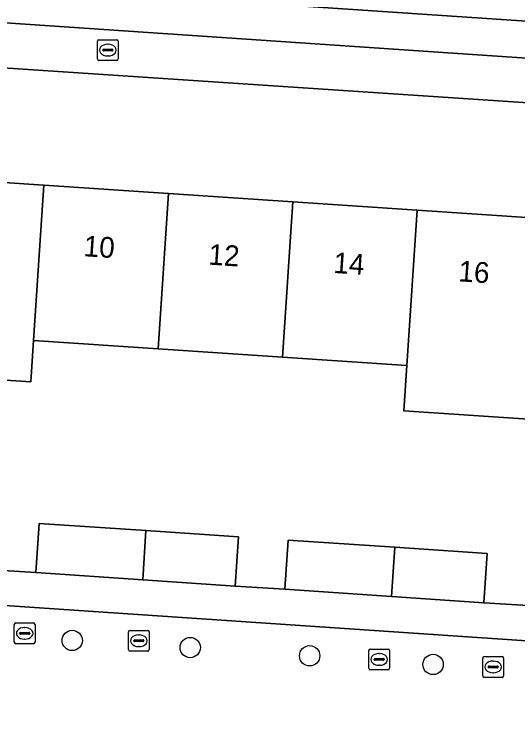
# Model space of a CAD drawing. Extents: x 161848 to 162726, y 385382 to 386521.
# Drawn here: x 162073.24 to 162097.46, y 385706.38 to 385740.75 of the extents above; entities that cross this region are included whole.
import ezdxf

# ---------------------------------------------------------------- set-up
doc = ezdxf.new("R2010")
doc.units = 0
for name, color, linetype in [('IMGEO_Boom', 7, 'Continuous'), ('IMGEO_Brandkraan', 7, 'Continuous'), ('IMGEO_Erf', 7, 'Continuous'), ('IMGEO_Kolk', 7, 'Continuous'), ('IMGEO_Pand', 7, 'Continuous'), ('IMGEO_Pand_nummerreeks', 7, 'Continuous'), ('IMGEO_Parkeervlak_open', 7, 'Continuous'), ('IMGEO_Rijbaan_lokaal_gesloten', 7, 'Continuous'), ('IMGEO_Voetpad_open', 7, 'Continuous')]:
    doc.layers.add(name, color=color, linetype=linetype)

msp = doc.modelspace()

# ---------------------------------------------------------------- linework, layer by layer
at = {"layer": 'IMGEO_Boom'}
for centre in [(162076.032, 385710.625), (162081.706, 385710.283), (162087.454, 385709.885), (162093.389, 385709.468)]:
    msp.add_circle(centre, 0.489, dxfattribs=at)
at = {"layer": 'IMGEO_Brandkraan'}
for p, q in [((162077.243, 385738.602), (162077.243, 385739.454)), ((162077.318, 385739.528), (162078.17, 385739.528)), ((162077.731, 385739.308), (162077.756, 385739.308)), ((162078.244, 385739.454), (162078.244, 385738.602)), ((162077.502, 385739.022), (162077.502, 385739.034)), ((162077.94, 385738.985), (162077.542, 385738.985)), ((162077.545, 385739.071), (162077.943, 385739.071)), ((162077.986, 385739.034), (162077.986, 385739.022)), ((162077.754, 385738.748), (162077.729, 385738.748)), ((162078.17, 385738.528), (162077.318, 385738.528))]:
    msp.add_line(p, q, dxfattribs=at)
for points in [[(162077.243, 385738.602), (162077.243, 385739.454)], [(162077.318, 385739.528), (162078.17, 385739.528)], [(162078.244, 385739.454), (162078.244, 385738.602)], [(162078.17, 385738.528), (162077.318, 385738.528)]]:
    msp.add_lwpolyline(points, dxfattribs=at)
for centre, radius, start, end in [((162077.32, 385739.452), 0.0765, 91.552, 178.448), ((162077.32, 385739.452), 0.0765, 91.552, 178.448), ((162078.168, 385739.452), 0.0765, 1.552, 88.448), ((162078.168, 385739.452), 0.0765, 1.552, 88.448), ((162077.542, 385739.031), 0.0403, 85.8775, 175.7526), ((162077.539, 385739.021), 0.0366, 178.938, 274.7102), ((162077.943, 385739.028), 0.043, 264.8664, 352.4533), ((162077.947, 385739.033), 0.0386, 1.7309, 96.639), ((162077.32, 385738.604), 0.0765, 181.552, 268.448), ((162077.32, 385738.604), 0.0765, 181.552, 268.448), ((162078.168, 385738.604), 0.0765, 271.552, 358.448), ((162078.168, 385738.604), 0.0765, 271.552, 358.448)]:
    msp.add_arc(centre, radius, start, end, dxfattribs=at)
for centre, major_axis, ratio, start_param, end_param in [((162077.73, 385739.028), (-0.387, 0.002), 0.722429, 4.712389, 7.853982), ((162077.755, 385739.028), (-0.39, 0.002), 0.717154, 1.570796, 4.712389)]:
    msp.add_ellipse(centre, major_axis=major_axis, ratio=ratio, start_param=start_param, end_param=end_param, dxfattribs=at)
at = {"layer": 'IMGEO_Erf'}
for points in [[(162115.981, 385735.292), (162050.825, 385739.638), (162050.459, 385734.147), (162056.714, 385733.728), (162062.7, 385733.327), (162068.685, 385732.927), (162074.671, 385732.526), (162080.657, 385732.125), (162086.643, 385731.724), (162092.627, 385731.324), (162098.613, 385730.923), (162104.599, 385730.522), (162110.585, 385730.121), (162116.577, 385729.72), (162116.083, 385722.272), (162115.943, 385720.163), (162109.926, 385720.563), (162103.965, 385720.958), (162101.048, 385721.151), (162101.188, 385723.259), (162098.118, 385723.463), (162097.973, 385721.267), (162091.987, 385721.664), (162092.132, 385723.86)], [(162071.896, 385714.042), (162074.284, 385713.89), (162074.445, 385716.256), (162079.58, 385715.908), (162084.029, 385715.606), (162083.868, 385713.24), (162086.254, 385713.089), (162086.415, 385715.455), (162091.552, 385715.107), (162095.999, 385714.805), (162095.838, 385712.439), (162098.226, 385712.287), (162098.387, 385714.653), (162103.522, 385714.305), (162107.971, 385714.003), (162107.81, 385711.637), (162109.055, 385711.543), (162109.275, 385714.458), (162117.352, 385713.847), (162118.056, 385724.2), (162118.638, 385732.761)], [(162092.132, 385723.86), (162086.147, 385724.257), (162080.161, 385724.654), (162074.176, 385725.051), (162074.044, 385723.068), (162068.058, 385723.465)]]:
    msp.add_lwpolyline(points, dxfattribs=at)
msp.add_lwpolyline([(162103.379, 385708.994), (162108.35, 385708.642), (162117.001, 385708.064), (162117.085, 385709.313), (162057.615, 385713.34), (162056.66, 385698.935), (162057.566, 385698.956), (162056.491, 385681.053), (162055.347, 385681.13), (162038.387, 385682.266), (162038.412, 385682.641), (162036.684, 385682.769), (162034.52, 385682.885), (162034.495, 385682.526), (162034.17, 385677.885), (162058.2, 385676.103), (162110.912, 385672.522), (162111.19, 385677.357), (162106.241, 385677.689), (162101.257, 385678.025)], close=True, dxfattribs=at)
at = {"layer": 'IMGEO_Kolk'}
for p, q in [((162073.319, 385711.465), (162074.171, 385711.465)), ((162073.244, 385710.539), (162073.244, 385711.391)), ((162073.732, 385711.245), (162073.757, 385711.245)), ((162074.245, 385711.391), (162074.245, 385710.539)), ((162073.503, 385710.959), (162073.503, 385710.971)), ((162073.941, 385710.922), (162073.543, 385710.922)), ((162073.546, 385711.008), (162073.944, 385711.008)), ((162073.987, 385710.971), (162073.987, 385710.959)), ((162078.738, 385710.184), (162078.738, 385711.036)), ((162078.813, 385711.11), (162079.665, 385711.11)), ((162079.226, 385710.89), (162079.251, 385710.89)), ((162079.739, 385711.036), (162079.739, 385710.184)), ((162074.171, 385710.465), (162073.319, 385710.465)), ((162073.755, 385710.685), (162073.73, 385710.685)), ((162078.997, 385710.604), (162078.997, 385710.616)), ((162079.435, 385710.567), (162079.037, 385710.567)), ((162079.04, 385710.653), (162079.438, 385710.653)), ((162079.481, 385710.616), (162079.481, 385710.604)), ((162079.665, 385710.11), (162078.813, 385710.11)), ((162079.249, 385710.33), (162079.224, 385710.33)), ((162090.299, 385709.286), (162090.299, 385710.138)), ((162090.374, 385710.212), (162091.226, 385710.212)), ((162091.3, 385710.138), (162091.3, 385709.286)), ((162090.601, 385709.755), (162090.999, 385709.755)), ((162090.787, 385709.992), (162090.812, 385709.992)), ((162095.781, 385708.924), (162095.781, 385709.776)), ((162095.856, 385709.85), (162096.708, 385709.85)), ((162096.782, 385709.776), (162096.782, 385708.924)), ((162090.558, 385709.706), (162090.558, 385709.718)), ((162090.996, 385709.669), (162090.598, 385709.669)), ((162090.81, 385709.432), (162090.785, 385709.432)), ((162091.042, 385709.718), (162091.042, 385709.706)), ((162096.269, 385709.63), (162096.294, 385709.63)), ((162091.226, 385709.212), (162090.374, 385709.212)), ((162096.04, 385709.344), (162096.04, 385709.356)), ((162096.478, 385709.307), (162096.08, 385709.307)), ((162096.083, 385709.393), (162096.481, 385709.393)), ((162096.292, 385709.07), (162096.267, 385709.07)), ((162096.524, 385709.356), (162096.524, 385709.344)), ((162096.708, 385708.85), (162095.856, 385708.85))]:
    msp.add_line(p, q, dxfattribs=at)
for points in [[(162073.319, 385711.465), (162074.171, 385711.465)], [(162073.244, 385710.539), (162073.244, 385711.391)], [(162074.245, 385711.391), (162074.245, 385710.539)], [(162078.738, 385710.184), (162078.738, 385711.036)], [(162078.813, 385711.11), (162079.665, 385711.11)], [(162079.739, 385711.036), (162079.739, 385710.184)], [(162074.171, 385710.465), (162073.319, 385710.465)], [(162079.665, 385710.11), (162078.813, 385710.11)], [(162090.299, 385709.286), (162090.299, 385710.138)], [(162090.374, 385710.212), (162091.226, 385710.212)], [(162091.3, 385710.138), (162091.3, 385709.286)], [(162095.781, 385708.924), (162095.781, 385709.776)], [(162095.856, 385709.85), (162096.708, 385709.85)], [(162096.782, 385709.776), (162096.782, 385708.924)], [(162091.226, 385709.212), (162090.374, 385709.212)], [(162096.708, 385708.85), (162095.856, 385708.85)]]:
    msp.add_lwpolyline(points, dxfattribs=at)
for centre, radius, start, end in [((162073.321, 385711.389), 0.0765, 91.552, 178.448), ((162073.321, 385711.389), 0.0765, 91.552, 178.448), ((162074.169, 385711.389), 0.0765, 1.552, 88.448), ((162074.169, 385711.389), 0.0765, 1.552, 88.448), ((162073.543, 385710.968), 0.0403, 85.8775, 175.7526), ((162073.54, 385710.958), 0.0366, 178.938, 274.7102), ((162073.944, 385710.965), 0.043, 264.8664, 352.4533), ((162073.948, 385710.97), 0.0386, 1.7309, 96.639), ((162078.815, 385711.034), 0.0765, 91.552, 178.448), ((162078.815, 385711.034), 0.0765, 91.552, 178.448), ((162079.663, 385711.034), 0.0765, 1.552, 88.448), ((162079.663, 385711.034), 0.0765, 1.552, 88.448), ((162073.321, 385710.541), 0.0765, 181.552, 268.448), ((162073.321, 385710.541), 0.0765, 181.552, 268.448), ((162074.169, 385710.541), 0.0765, 271.552, 358.448), ((162074.169, 385710.541), 0.0765, 271.552, 358.448), ((162079.037, 385710.613), 0.0403, 85.8775, 175.7526), ((162079.034, 385710.603), 0.0366, 178.938, 274.7102), ((162079.438, 385710.61), 0.043, 264.8664, 352.4533), ((162079.442, 385710.615), 0.0386, 1.7309, 96.639), ((162078.815, 385710.186), 0.0765, 181.552, 268.448), ((162078.815, 385710.186), 0.0765, 181.552, 268.448), ((162079.663, 385710.186), 0.0765, 271.552, 358.448), ((162079.663, 385710.186), 0.0765, 271.552, 358.448), ((162090.376, 385710.136), 0.0765, 91.552, 178.448), ((162090.376, 385710.136), 0.0765, 91.552, 178.448), ((162091.224, 385710.136), 0.0765, 1.552, 88.448), ((162091.224, 385710.136), 0.0765, 1.552, 88.448), ((162090.598, 385709.715), 0.0403, 85.8775, 175.7526), ((162091.003, 385709.717), 0.0386, 1.7309, 96.639), ((162095.858, 385709.774), 0.0765, 91.552, 178.448), ((162095.858, 385709.774), 0.0765, 91.552, 178.448), ((162096.706, 385709.774), 0.0765, 1.552, 88.448), ((162096.706, 385709.774), 0.0765, 1.552, 88.448), ((162090.595, 385709.705), 0.0366, 178.938, 274.7102), ((162090.999, 385709.712), 0.043, 264.8664, 352.4533), ((162090.376, 385709.288), 0.0765, 181.552, 268.448), ((162090.376, 385709.288), 0.0765, 181.552, 268.448), ((162091.224, 385709.288), 0.0765, 271.552, 358.448), ((162091.224, 385709.288), 0.0765, 271.552, 358.448), ((162096.08, 385709.353), 0.0403, 85.8775, 175.7526), ((162096.077, 385709.343), 0.0366, 178.938, 274.7102), ((162096.481, 385709.35), 0.043, 264.8664, 352.4533), ((162096.485, 385709.355), 0.0386, 1.7309, 96.639), ((162095.858, 385708.926), 0.0765, 181.552, 268.448), ((162095.858, 385708.926), 0.0765, 181.552, 268.448), ((162096.706, 385708.926), 0.0765, 271.552, 358.448), ((162096.706, 385708.926), 0.0765, 271.552, 358.448)]:
    msp.add_arc(centre, radius, start, end, dxfattribs=at)
for centre, major_axis, ratio, start_param, end_param in [((162073.731, 385710.965), (-0.387, 0.002), 0.722429, 4.712389, 7.853982), ((162073.756, 385710.965), (-0.39, 0.002), 0.717154, 1.570796, 4.712389), ((162079.225, 385710.61), (-0.387, 0.002), 0.722429, 4.712389, 7.853982), ((162079.25, 385710.61), (-0.39, 0.002), 0.717154, 1.570796, 4.712389), ((162090.786, 385709.712), (-0.387, 0.002), 0.722429, 4.712389, 7.853982), ((162090.811, 385709.712), (-0.39, 0.002), 0.717154, 1.570796, 4.712389), ((162096.268, 385709.35), (-0.387, 0.002), 0.722429, 4.712389, 7.853982), ((162096.293, 385709.35), (-0.39, 0.002), 0.717154, 1.570796, 4.712389)]:
    msp.add_ellipse(centre, major_axis=major_axis, ratio=ratio, start_param=start_param, end_param=end_param, dxfattribs=at)
at = {"layer": 'IMGEO_Pand'}
for points in [[(162074.671, 385732.526), (162068.685, 385732.927), (162068.058, 385723.465), (162074.044, 385723.068), (162074.176, 385725.051)], [(162080.657, 385732.125), (162074.671, 385732.526), (162074.176, 385725.051), (162080.161, 385724.654)], [(162080.161, 385724.654), (162086.147, 385724.257), (162086.643, 385731.724), (162080.657, 385732.125)], [(162086.147, 385724.257), (162092.132, 385723.86), (162092.627, 385731.324), (162086.643, 385731.724)], [(162092.132, 385723.86), (162091.987, 385721.664), (162097.973, 385721.267), (162098.118, 385723.463), (162098.613, 385730.923), (162092.627, 385731.324)], [(162074.445, 385716.256), (162074.284, 385713.89), (162079.423, 385713.542), (162079.58, 385715.908)], [(162083.868, 385713.24), (162084.029, 385715.606), (162079.58, 385715.908), (162079.423, 385713.542)], [(162086.415, 385715.455), (162086.254, 385713.089), (162091.395, 385712.741), (162091.552, 385715.107)], [(162095.838, 385712.439), (162095.999, 385714.805), (162091.552, 385715.107), (162091.395, 385712.741)]]:
    msp.add_lwpolyline(points, close=True, dxfattribs=at)
at = {"layer": 'IMGEO_Parkeervlak_open'}
for points in [[(162116.37, 385739.177), (162103.122, 385740.074), (162077.603, 385741.806), (162051.772, 385743.57)], [(162054.362, 385741.601), (162100.969, 385738.434)]]:
    msp.add_lwpolyline(points, dxfattribs=at)
at = {"layer": 'IMGEO_Rijbaan_lokaal_gesloten'}
msp.add_lwpolyline([(162186.826, 385734.287), (162184.65, 385734.497), (162177.9, 385735.148), (162157.058, 385737.16), (162131.864, 385739.672), (162089.667, 385742.424), (162064.724, 385744.182), (162040.807, 385745.812), (162040.667, 385744.254), (162045.788, 385743.892), (162049.86, 385743.699), (162050.52, 385743.664), (162051.772, 385743.57), (162077.603, 385741.806), (162103.122, 385740.074), (162116.37, 385739.177), (162118.946, 385739.003), (162130.535, 385738.163), (162140.975, 385737.205), (162162.35, 385735.171), (162179.488, 385733.543), (162180.737, 385733.424), (162184.825, 385733.037), (162186.96, 385732.835)], close=True, dxfattribs=at)
at = {"layer": 'IMGEO_Voetpad_open'}
for points in [[(162100.969, 385738.434), (162054.362, 385741.601)], [(162035.75, 385740.46), (162040.42, 385740.146), (162045.739, 385739.976), (162049.431, 385739.731), (162050.825, 385739.638), (162115.981, 385735.292)], [(162057.615, 385713.34), (162117.085, 385709.313), (162117.118, 385710.751), (162109.041, 385711.363), (162109.055, 385711.543), (162107.81, 385711.637), (162103.365, 385711.939), (162098.226, 385712.287), (162095.838, 385712.439), (162091.395, 385712.741), (162086.254, 385713.089), (162083.868, 385713.24), (162079.423, 385713.542), (162074.284, 385713.89), (162071.896, 385714.042)]]:
    msp.add_lwpolyline(points, dxfattribs=at)

# ---------------------------------------------------------------- texts
at = {"layer": 'IMGEO_Pand_nummerreeks'}
for s, rotation, p in [('10', 356.1694, (162076.558, 385729.112)), ('12', 356.1694, (162082.562, 385728.71)), ('14', 356.1694, (162088.576, 385728.308)), ('16', 356.1669, (162094.587, 385727.905))]:
    msp.add_text(s, height=1, rotation=rotation, dxfattribs=at).set_placement(p)

doc.saveas('drawing.dxf')
